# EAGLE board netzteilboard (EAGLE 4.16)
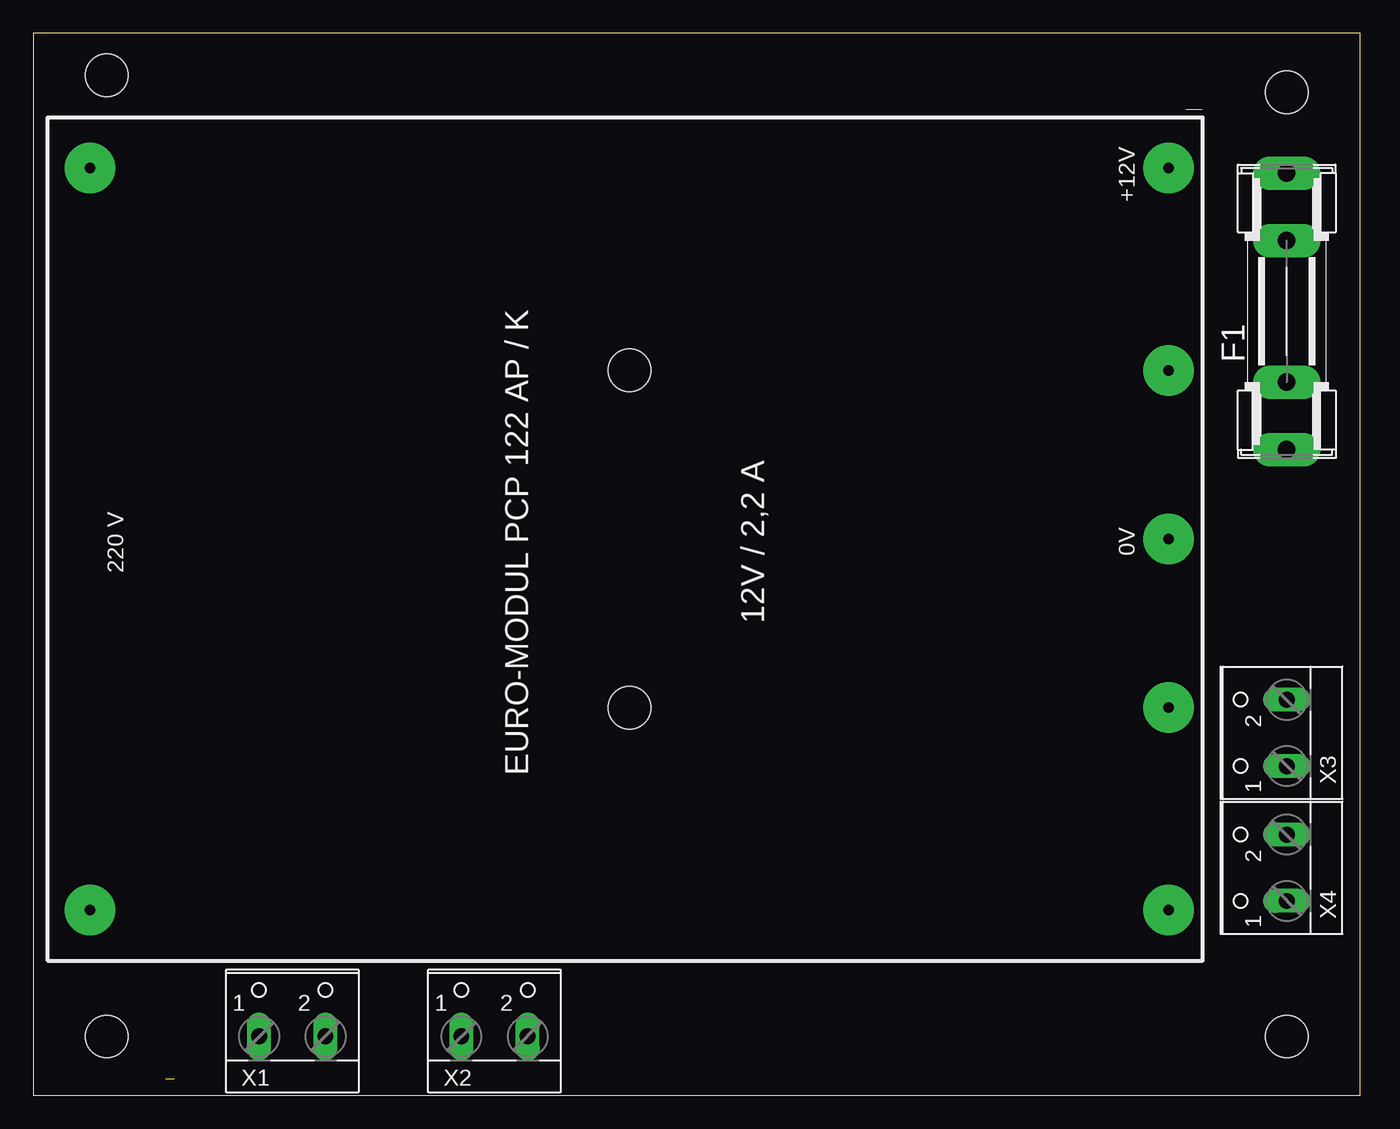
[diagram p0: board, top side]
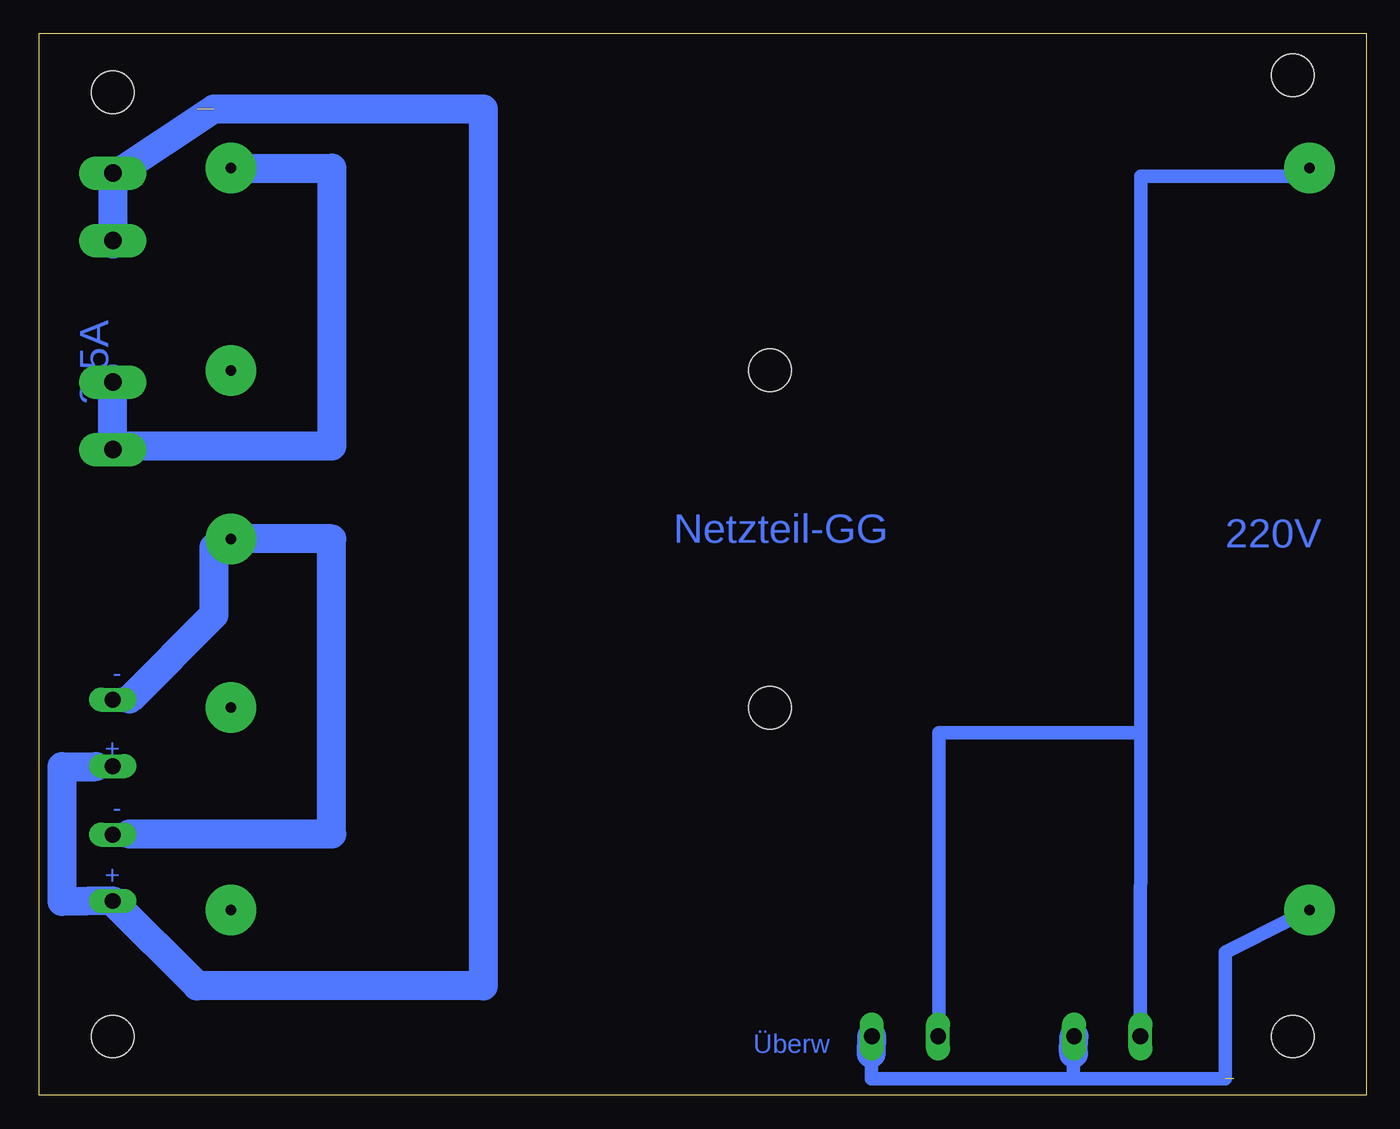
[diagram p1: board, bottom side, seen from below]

Size 100 x 80 mm. Coordinates in mm from the lower left corner, seen from the top.
Outline: 0,0 100,0 100,80 0,80 0,0
Copper layers (1*16): Top 0.035mm / dielectric 1.5mm / Bottom 0.035mm
Design rules "default": minimum track width 10mil, minimum drill 24mil, track to track 8mil, track to pad 8mil, pad to pad 8mil, via to via 8mil, smd to smd 8mil, copper to edge 40mil, drill to drill 8mil, minimum pad ring 10mil, minimum via ring 8mil, stop-mask expansion 4mil, vias tented up to drill 0mil, thermal gap 10mil
Holes 3.2 mm at 5.55,76.83 5.55,4.44 94.45,4.44 94.45,75.56

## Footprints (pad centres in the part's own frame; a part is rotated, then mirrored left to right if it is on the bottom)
SHK20L = drill 1.321 pad 2.54 long: 1A -10.414,0; 1B -5.334,0; 2A 10.414,0; 2B 5.334,0
EURO-MODUL = drill 0.8 pad 3.81 round: +12 35.56,-68.58; AC+ -20.32,12.7; AC- 35.56,12.7; COM 7.62,-68.58; NC -20.32,-68.58; P$6 -5.08,-68.58; P$7 20.32,-68.58 | hole 3.2: -5.08,-27.94; 20.32,-27.94
W237-102 = drill 1.194 long: 1 -2.5,-1.27; 2 2.5,-1.27

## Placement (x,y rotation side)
F1  [SHK20L]  94.45,59.05 90 top
U$1  EURO-MODUL  [EURO-MODUL]  16.98,34.29 90 top
X1  [W237-102]  19.52,5.71 0 top
X2  [W237-102]  34.76,5.71 0 top
X3  [W237-102]  93.18,27.3 90 top
X4  [W237-102]  93.18,17.14 90 top

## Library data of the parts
F1 = fuse
U$1 = euro-modul-netzteil
X1-X4 = con-wago-500

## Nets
N$5: U$1.AC- X1.1 X2.1
N$6: U$1.AC+ X1.2 X2.2
N$7: F1.1A U$1.+12
N$8: F1.2A X3.1 X4.1
N$9: U$1.COM X3.2 X4.2

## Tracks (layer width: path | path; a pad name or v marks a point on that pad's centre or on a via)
N$5
  Bottom 0.254: 32.22,5.71 X2.1 | 5.55,69.21 U$1.AC-
  Bottom 1.016: 16.98,27.3 32.22,27.3 32.22,5.71 | 5.55,69.21 16.98,69.21 16.98,27.3 | X1.1 16.98,27.3
N$6  (1 unrouted)
  Bottom 0.254: 5.55,13.33 U$1.AC+
  Bottom 1.016: 22.06,1.27 22.06,3.17 | 22.06,1.27 37.3,1.27 37.3,3.17 | 5.55,13.33 10.63,10.79 10.63,1.27 22.06,1.27
  Bottom 2.184: 22.06,3.17 X1.2 | 37.3,3.17 X2.2
N$7
  Bottom 2.184: 94.45,48.89 F1.1A | 94.45,48.89 77.94,48.89 77.94,69.84 U$1.+12 | 94.45,48.89 94.45,53.97
N$8  (1 unrouted)
  Bottom 0.254: 95.72,24.76 X3.1 | 88.1,73.66 88.1,74.29
  Bottom 2.184: 95.72,24.76 98.26,24.76 98.26,14.6 X4.1 94.45,14.6 88.1,8.25 66.51,8.25 66.51,74.29 86.83,74.29 94.45,69.21 | 94.45,69.21 94.45,64.13 | 94.45,69.21 F1.2A
N$9
  Bottom 0.254: 93.18,19.68 X4.2 | 93.18,29.84 X3.2 | 86.83,41.27 86.07,41.65 U$1.COM
  Bottom 2.184: 86.83,41.27 86.83,36.19 93.18,29.84 | 93.18,19.68 77.94,19.68 77.94,41.91 86.19,41.91 86.19,41.65 86.07,41.65

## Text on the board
Bottom: 2,5A | Netzteil-GG | 220V | - | + | - | + | Überw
